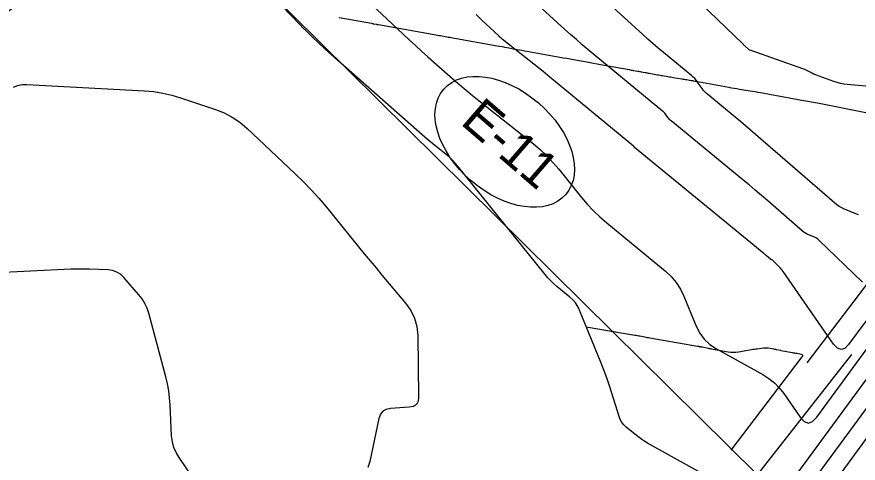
# Model space of a CAD drawing. Extents: x 1005228 to 1008882, y 1883389 to 1885754.
# Drawn here: x 1007598.8 to 1007741.8, y 1884701.7 to 1884777.6 of the extents above; entities that cross this region are included whole.
import ezdxf

# ---------------------------------------------------------------- set-up
doc = ezdxf.new("R2010")
doc.units = 0
for name, color, linetype in [('ATDIMS', 7, 'Continuous'), ('C-ANNO-NOTE', 7, 'Continuous'), ('R_Erosion', 7, 'Continuous'), ('S_BRIDGE', 7, 'Continuous'), ('TSOBSTACLE', 7, 'Continuous')]:
    doc.layers.add(name, color=color, linetype=linetype)

msp = doc.modelspace()

# ---------------------------------------------------------------- linework, layer by layer
at = {"layer": 'ATDIMS'}
for points in [[(1007653.58, 1884777.44), (1007659.11, 1884776.45), (1007659.21, 1884776.43), (1007659.3, 1884776.41), (1007659.4, 1884776.39), (1007659.5, 1884776.38), (1007659.88, 1884776.31), (1007659.98, 1884776.29), (1007660.07, 1884776.27), (1007660.17, 1884776.26), (1007660.27, 1884776.24), (1007669.76, 1884774.54), (1007670.02, 1884774.49), (1007670.29, 1884774.44), (1007670.55, 1884774.39), (1007670.82, 1884774.35), (1007671.87, 1884774.16), (1007672.14, 1884774.11), (1007672.4, 1884774.07), (1007672.67, 1884774.02), (1007672.93, 1884773.97), (1007680.44, 1884772.63), (1007680.86, 1884772.56), (1007681.28, 1884772.48), (1007681.7, 1884772.41), (1007682.12, 1884772.33), (1007683.81, 1884772.02), (1007684.23, 1884771.95), (1007684.65, 1884771.87), (1007685.07, 1884771.79), (1007685.49, 1884771.72), (1007691.11, 1884770.7), (1007691.68, 1884770.6), (1007692.26, 1884770.5), (1007692.83, 1884770.39), (1007693.4, 1884770.29), (1007695.69, 1884769.88), (1007696.27, 1884769.78), (1007696.84, 1884769.68), (1007697.41, 1884769.58), (1007697.98, 1884769.47), (1007702.89, 1884768.57), (1007703.06, 1884768.54), (1007703.23, 1884768.51), (1007703.4, 1884768.48), (1007703.57, 1884768.45), (1007704.26, 1884768.32), (1007704.43, 1884768.29), (1007704.6, 1884768.26), (1007704.76, 1884768.23), (1007704.93, 1884768.2), (1007705.61, 1884768.09), (1007705.78, 1884768.06), (1007705.95, 1884768.03), (1007706.11, 1884768), (1007706.28, 1884767.97), (1007707.67, 1884767.71), (1007707.89, 1884767.67), (1007708.12, 1884767.63), (1007708.34, 1884767.59), (1007708.56, 1884767.55), (1007709.46, 1884767.41), (1007709.69, 1884767.37), (1007709.91, 1884767.33), (1007710.13, 1884767.29), (1007710.36, 1884767.26), (1007711.8, 1884767.01), (1007712, 1884766.97), (1007712.21, 1884766.94), (1007712.41, 1884766.9), (1007712.61, 1884766.87), (1007713.41, 1884766.74), (1007713.61, 1884766.71), (1007713.81, 1884766.68), (1007714.02, 1884766.64), (1007714.22, 1884766.61), (1007719.8, 1884765.58), (1007720.24, 1884765.5), (1007720.69, 1884765.42), (1007721.14, 1884765.35), (1007721.6, 1884765.27), (1007723.4, 1884764.98), (1007723.85, 1884764.91), (1007724.3, 1884764.83), (1007724.75, 1884764.75), (1007725.2, 1884764.67), (1007731.56, 1884763.48), (1007731.88, 1884763.42), (1007732.21, 1884763.36), (1007732.53, 1884763.31), (1007732.86, 1884763.25), (1007734.16, 1884763.03), (1007734.49, 1884762.97), (1007734.81, 1884762.91), (1007735.14, 1884762.85), (1007735.46, 1884762.79), (1007743.37, 1884761.22)], [(1007763.17, 1884758.31), (1007733.06, 1884718.71)]]:
    msp.add_lwpolyline(points, dxfattribs=at)
at = {"layer": 'C-ANNO-NOTE'}
for points in [[(1007741.81, 1884743.86), (1007741.35, 1884744.07), (1007739.45, 1884744.85), (1007738.99, 1884745.06), (1007738.55, 1884745.31), (1007738.13, 1884745.59), (1007737.73, 1884745.91), (1007724.35, 1884757.57), (1007723.49, 1884758.31), (1007722.64, 1884759.04), (1007721.77, 1884759.77), (1007720.9, 1884760.49), (1007716.21, 1884764.34), (1007715.95, 1884764.57), (1007715.7, 1884764.82), (1007715.47, 1884765.08), (1007715.26, 1884765.36), (1007714.44, 1884766.51), (1007714.23, 1884766.79), (1007714, 1884767.05), (1007713.75, 1884767.3), (1007713.49, 1884767.53), (1007708.69, 1884771.49), (1007707.8, 1884772.23), (1007706.93, 1884772.98), (1007706.06, 1884773.75), (1007705.2, 1884774.52), (1007692.43, 1884786.2)], [(1007743.67, 1884765.73), (1007739.93, 1884766.06), (1007739.35, 1884766.13), (1007738.78, 1884766.24), (1007738.21, 1884766.38), (1007737.66, 1884766.56), (1007734.5, 1884767.69), (1007734.42, 1884767.72), (1007734.35, 1884767.76), (1007734.28, 1884767.79), (1007734.21, 1884767.83), (1007733.92, 1884767.99), (1007733.85, 1884768.03), (1007733.78, 1884768.07), (1007733.71, 1884768.1), (1007733.63, 1884768.14), (1007732.96, 1884768.49), (1007732.83, 1884768.55), (1007732.69, 1884768.62), (1007732.55, 1884768.67), (1007732.4, 1884768.73), (1007723.45, 1884771.87), (1007723.43, 1884771.87), (1007723.41, 1884771.88), (1007723.39, 1884771.89), (1007723.37, 1884771.89), (1007723.27, 1884771.92), (1007723.27, 1884771.92), (1007723.26, 1884771.92), (1007723.25, 1884771.93), (1007723.25, 1884771.94), (1007723.23, 1884771.96), (1007723.22, 1884771.97), (1007723.22, 1884771.98), (1007723.21, 1884771.98), (1007723.21, 1884771.99), (1007722.58, 1884772.56), (1007722.48, 1884772.66), (1007722.37, 1884772.76), (1007722.27, 1884772.86), (1007722.16, 1884772.96), (1007710.71, 1884784.09)], [(1007657.27, 1884781.42), (1007664.46, 1884774.63), (1007665.5, 1884773.64), (1007666.56, 1884772.67), (1007667.62, 1884771.71), (1007668.69, 1884770.75), (1007673, 1884766.96), (1007674.08, 1884766.01), (1007675.17, 1884765.09), (1007676.28, 1884764.17), (1007677.4, 1884763.27), (1007686.6, 1884755.95), (1007687.77, 1884754.97), (1007688.88, 1884753.92), (1007689.93, 1884752.81), (1007690.92, 1884751.65), (1007694.77, 1884746.86), (1007695.76, 1884745.69), (1007696.81, 1884744.57), (1007697.91, 1884743.52), (1007699.07, 1884742.51), (1007709.03, 1884734.33), (1007710.02, 1884733.41), (1007710.88, 1884732.39), (1007711.6, 1884731.27), (1007712.18, 1884730.06), (1007714.26, 1884724.98), (1007714.87, 1884723.79), (1007715.64, 1884722.75), (1007716.58, 1884721.86), (1007717.7, 1884721.11), (1007725.6, 1884716.71), (1007726.62, 1884716.06), (1007727.55, 1884715.32), (1007728.38, 1884714.47), (1007729.13, 1884713.51), (1007731.91, 1884709.5), (1007732.61, 1884708.74), (1007733.31, 1884708.48), (1007734.02, 1884708.72), (1007734.74, 1884709.46), (1007743.94, 1884722)], [(1007720.75, 1884696.86), (1007706, 1884705.08), (1007705.51, 1884705.37), (1007705.04, 1884705.68), (1007704.58, 1884706), (1007704.13, 1884706.35), (1007702.38, 1884707.79), (1007701.98, 1884708.17), (1007701.64, 1884708.6), (1007701.37, 1884709.08), (1007701.16, 1884709.59), (1007699.59, 1884714.63), (1007699.25, 1884715.64), (1007698.9, 1884716.65), (1007698.53, 1884717.65), (1007698.14, 1884718.64), (1007694.43, 1884727.68), (1007694.13, 1884728.31), (1007693.75, 1884728.9), (1007693.31, 1884729.43), (1007692.79, 1884729.91), (1007690.59, 1884731.72), (1007690.05, 1884732.18), (1007689.54, 1884732.67), (1007689.05, 1884733.19), (1007688.59, 1884733.73), (1007673.73, 1884752.22), (1007673.33, 1884752.69), (1007672.91, 1884753.14), (1007672.46, 1884753.56), (1007671.99, 1884753.95), (1007670.06, 1884755.49), (1007669.58, 1884755.88), (1007669.1, 1884756.27), (1007668.63, 1884756.67), (1007668.17, 1884757.08), (1007653.39, 1884770.11), (1007652.84, 1884770.61), (1007652.29, 1884771.1), (1007651.74, 1884771.61), (1007651.2, 1884772.11), (1007649.04, 1884774.15), (1007648.51, 1884774.67), (1007647.98, 1884775.19), (1007647.46, 1884775.71), (1007646.94, 1884776.25), (1007642.42, 1884781.01)], [(1007743.25, 1884726.06), (1007740.16, 1884721.84), (1007739.51, 1884721.18), (1007738.87, 1884720.97), (1007738.24, 1884721.2), (1007737.61, 1884721.88), (1007729.06, 1884734.23), (1007728.89, 1884734.45), (1007728.72, 1884734.66), (1007728.54, 1884734.87), (1007728.35, 1884735.06), (1007727.21, 1884736.16), (1007727.19, 1884736.18), (1007727.16, 1884736.2), (1007727.14, 1884736.21), (1007727.11, 1884736.23), (1007726.99, 1884736.27), (1007726.97, 1884736.28), (1007726.94, 1884736.3), (1007726.91, 1884736.32), (1007726.89, 1884736.34), (1007726.22, 1884736.92), (1007726.11, 1884737.02), (1007725.99, 1884737.12), (1007725.86, 1884737.22), (1007725.74, 1884737.32), (1007703.78, 1884755.36), (1007703.76, 1884755.37), (1007703.75, 1884755.39), (1007703.74, 1884755.4), (1007703.72, 1884755.42), (1007703.67, 1884755.49), (1007703.66, 1884755.51), (1007703.65, 1884755.52), (1007703.63, 1884755.54), (1007703.62, 1884755.55), (1007689.03, 1884767.59), (1007688.25, 1884768.23), (1007687.48, 1884768.86), (1007686.7, 1884769.49), (1007685.91, 1884770.11), (1007681.32, 1884773.77), (1007681.26, 1884773.81), (1007681.21, 1884773.86), (1007681.16, 1884773.9), (1007681.11, 1884773.94), (1007680.91, 1884774.12), (1007680.86, 1884774.17), (1007680.81, 1884774.21), (1007680.76, 1884774.26), (1007680.71, 1884774.31), (1007677.85, 1884777.01), (1007677.36, 1884777.47), (1007676.86, 1884777.93)], [(1007598.26, 1884765.61), (1007598.99, 1884765.89), (1007599.75, 1884766.04), (1007600.54, 1884766.05), (1007620.54, 1884764.98), (1007622.1, 1884764.84), (1007623.64, 1884764.6), (1007625.16, 1884764.25), (1007626.66, 1884763.8), (1007632.62, 1884761.79), (1007634.07, 1884761.21), (1007635.43, 1884760.49), (1007636.71, 1884759.63), (1007637.9, 1884758.63), (1007646.1, 1884750.93), (1007647.51, 1884749.57), (1007648.87, 1884748.15), (1007650.18, 1884746.7), (1007651.44, 1884745.19), (1007656.89, 1884738.46), (1007657.88, 1884737.25), (1007658.87, 1884736.05), (1007659.87, 1884734.85), (1007660.87, 1884733.65), (1007664.89, 1884728.87), (1007665.77, 1884727.63), (1007666.41, 1884726.3), (1007666.8, 1884724.88), (1007666.95, 1884723.36), (1007667.1, 1884712.89), (1007667.01, 1884712.18), (1007666.72, 1884711.66), (1007666.22, 1884711.32), (1007665.52, 1884711.18), (1007662.31, 1884710.96), (1007661.59, 1884710.81), (1007661.02, 1884710.48), (1007660.62, 1884709.97), (1007660.37, 1884709.28), (1007658.79, 1884701.95), (1007658.47, 1884700.94)], [(1007744.79, 1884718.15), (1007730.07, 1884698.09)], [(1007734.21, 1884698.73), (1007746.98, 1884716.13)]]:
    msp.add_lwpolyline(points, dxfattribs=at)
at = {"layer": 'R_Erosion'}
msp.add_lwpolyline([(1007479.35, 1884649.35), (1007490.06, 1884659.98), (1007582.04, 1884767.38), (1007608.23, 1884786.44), (1007622.73, 1884788.72), (1007640.54, 1884783.01), (1007724.67, 1884699.7), (1007740.7, 1884720.15)], dxfattribs=at)
msp.add_ellipse((1007681.73, 1884756.3), major_axis=(10.37, -8.95), ratio=0.638788, dxfattribs=at)
at = {"layer": 'S_BRIDGE'}
for points in [[(1007742.52, 1884732.43), (1007735.12, 1884739.57), (1007734.92, 1884739.74), (1007734.7, 1884739.9), (1007734.47, 1884740.04), (1007734.23, 1884740.15), (1007733.22, 1884740.56), (1007732.98, 1884740.67), (1007732.74, 1884740.81), (1007732.52, 1884740.96), (1007732.31, 1884741.12), (1007726.42, 1884746.26), (1007725.36, 1884747.17), (1007724.3, 1884748.07), (1007723.24, 1884748.97), (1007722.16, 1884749.86), (1007710, 1884759.85), (1007709.86, 1884759.97), (1007709.73, 1884760.1), (1007709.6, 1884760.24), (1007709.49, 1884760.39), (1007709.06, 1884761), (1007708.95, 1884761.15), (1007708.82, 1884761.29), (1007708.69, 1884761.42), (1007708.55, 1884761.54), (1007695.92, 1884771.96), (1007694.91, 1884772.81), (1007693.91, 1884773.67), (1007692.92, 1884774.54), (1007691.94, 1884775.42), (1007688.04, 1884778.99)], [(1007628.7, 1884699.27), (1007626.4, 1884702.6), (1007625.89, 1884703.45), (1007625.52, 1884704.35), (1007625.27, 1884705.3), (1007625.15, 1884706.29), (1007624.9, 1884711.57), (1007624.81, 1884712.78), (1007624.65, 1884713.98), (1007624.43, 1884715.17), (1007624.15, 1884716.35), (1007621.26, 1884727.15), (1007620.97, 1884728.01), (1007620.6, 1884728.82), (1007620.13, 1884729.58), (1007619.57, 1884730.3), (1007617, 1884733.25), (1007616.44, 1884733.78), (1007615.82, 1884734.16), (1007615.13, 1884734.41), (1007614.37, 1884734.51), (1007611.21, 1884734.63), (1007610.42, 1884734.65), (1007609.63, 1884734.66), (1007608.84, 1884734.65), (1007608.05, 1884734.62), (1007594.29, 1884733.98)], [(1007749.17, 1884714.12), (1007738.35, 1884699.36)]]:
    msp.add_lwpolyline(points, dxfattribs=at)
at = {"layer": 'TSOBSTACLE'}
msp.add_lwpolyline([(1007720.22, 1884703.89), (1007732.27, 1884719.73), (1007732.35, 1884719.87), (1007732.35, 1884719.98), (1007732.28, 1884720.07), (1007732.13, 1884720.12), (1007731.38, 1884720.28), (1007731.19, 1884720.32), (1007731, 1884720.35), (1007730.81, 1884720.39), (1007730.62, 1884720.42), (1007728.65, 1884720.78), (1007728.64, 1884720.78), (1007728.64, 1884720.78), (1007728.63, 1884720.79), (1007728.62, 1884720.8), (1007728.62, 1884720.8), (1007728.61, 1884720.8), (1007728.61, 1884720.8), (1007727.91, 1884720.95), (1007727.8, 1884720.97), (1007727.68, 1884720.99), (1007727.56, 1884721.01), (1007727.44, 1884721.04), (1007726.5, 1884721.2), (1007726.3, 1884721.23), (1007726.11, 1884721.24), (1007725.91, 1884721.24), (1007725.71, 1884721.22), (1007724.64, 1884721.07), (1007724.39, 1884721.04), (1007724.15, 1884721), (1007723.9, 1884720.96), (1007723.66, 1884720.92), (1007721.46, 1884720.55), (1007721.02, 1884720.49), (1007720.57, 1884720.48), (1007720.12, 1884720.5), (1007719.68, 1884720.56), (1007717.14, 1884721.01), (1007716.94, 1884721.05), (1007716.74, 1884721.08), (1007716.54, 1884721.12), (1007716.34, 1884721.16), (1007715.26, 1884721.38), (1007715.21, 1884721.39), (1007715.15, 1884721.4), (1007715.09, 1884721.41), (1007715.04, 1884721.42), (1007714.74, 1884721.46), (1007714.72, 1884721.46), (1007714.7, 1884721.47), (1007714.67, 1884721.47), (1007714.65, 1884721.47), (1007714.56, 1884721.49), (1007714.54, 1884721.49), (1007714.52, 1884721.49), (1007714.5, 1884721.5), (1007714.48, 1884721.5), (1007706.37, 1884722.91), (1007706.16, 1884722.95), (1007705.95, 1884722.99), (1007705.74, 1884723.03), (1007705.53, 1884723.07), (1007704.7, 1884723.23), (1007704.49, 1884723.27), (1007704.28, 1884723.31), (1007704.07, 1884723.35), (1007703.86, 1884723.38), (1007695.54, 1884724.8)], dxfattribs=at)

# ---------------------------------------------------------------- texts
at = {"layer": 'R_Erosion'}
msp.add_text('E-11', height=6.25, rotation=319.1818, dxfattribs=at).set_placement((1007674.02, 1884759.44))

doc.saveas('drawing.dxf')
